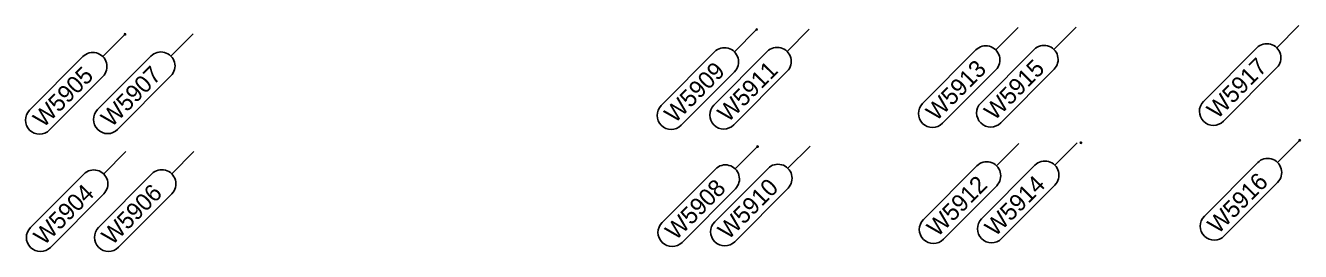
# Model space of a CAD drawing. Extents: x 12479652 to 12487250, y 9842710 to 9846560.
# Drawn here: x 12483353.2 to 12483446.2, y 9842743 to 9842759.5 of the extents above; entities that cross this region are included whole.
import ezdxf

# ---------------------------------------------------------------- set-up
doc = ezdxf.new("R2010")
doc.units = 0
doc.layers.add('_CIVIL_CONSTRUCTION', color=7, linetype='Continuous')
doc.layers.add('TextAlignmentLrg', color=7, linetype='Continuous')

msp = doc.modelspace()

# ---------------------------------------------------------------- linework, layer by layer
at = {"layer": '_CIVIL_CONSTRUCTION'}
for p, q in [((12483406.501, 9842759.196), (12483404.879, 9842757.565)), ((12483410.341, 9842759.225), (12483408.719, 9842757.594)), ((12483425.562, 9842759.339), (12483423.94, 9842757.707)), ((12483429.807, 9842759.37), (12483428.185, 9842757.739)), ((12483446.053, 9842759.492), (12483444.432, 9842757.86)), ((12483360.435, 9842758.852), (12483358.813, 9842757.221)), ((12483365.398, 9842758.889), (12483363.776, 9842757.258)), ((12483353.473, 9842753.304), (12483357.362, 9842757.216)), ((12483358.436, 9842753.341), (12483362.325, 9842757.254)), ((12483399.539, 9842753.648), (12483403.429, 9842757.561)), ((12483403.379, 9842753.676), (12483407.268, 9842757.589)), ((12483418.6, 9842753.79), (12483422.49, 9842757.703)), ((12483422.845, 9842753.822), (12483426.734, 9842757.735)), ((12483439.091, 9842753.943), (12483442.981, 9842757.856)), ((12483404.884, 9842756.114), (12483400.994, 9842752.201)), ((12483408.724, 9842756.143), (12483404.834, 9842752.23)), ((12483423.945, 9842756.256), (12483420.055, 9842752.344)), ((12483428.189, 9842756.288), (12483424.3, 9842752.375)), ((12483444.436, 9842756.409), (12483440.546, 9842752.497)), ((12483358.817, 9842755.77), (12483354.928, 9842751.857)), ((12483363.78, 9842755.807), (12483359.891, 9842751.894)), ((12483406.565, 9842750.641), (12483404.943, 9842749.009)), ((12483410.405, 9842750.686), (12483408.783, 9842749.055)), ((12483425.625, 9842750.867), (12483424.004, 9842749.236)), ((12483429.87, 9842750.918), (12483428.248, 9842749.286)), ((12483446.116, 9842751.11), (12483444.494, 9842749.479)), ((12483360.499, 9842750.274), (12483358.877, 9842748.643)), ((12483365.462, 9842750.286), (12483363.84, 9842748.655)), ((12483399.603, 9842745.092), (12483403.493, 9842749.005)), ((12483403.443, 9842745.138), (12483407.332, 9842749.051)), ((12483418.663, 9842745.319), (12483422.553, 9842749.231)), ((12483422.908, 9842745.369), (12483426.797, 9842749.282)), ((12483439.154, 9842745.562), (12483443.043, 9842749.475)), ((12483353.537, 9842744.726), (12483357.426, 9842748.639)), ((12483358.5, 9842744.738), (12483362.389, 9842748.65)), ((12483424.008, 9842747.785), (12483420.118, 9842743.872)), ((12483428.252, 9842747.835), (12483424.363, 9842743.923)), ((12483444.498, 9842748.028), (12483440.609, 9842744.116)), ((12483358.881, 9842747.192), (12483354.992, 9842743.279)), ((12483363.845, 9842747.204), (12483359.955, 9842743.291)), ((12483404.948, 9842747.559), (12483401.058, 9842743.646)), ((12483408.787, 9842747.604), (12483404.898, 9842743.691))]:
    msp.add_line(p, q, dxfattribs=at)
for centre, start, end in [((12483423.217, 9842756.98), 315.17021, 135.17022), ((12483427.462, 9842757.011), 315.17021, 135.17022), ((12483443.708, 9842757.133), 315.17021, 135.17022), ((12483358.09, 9842756.493), 315.17021, 135.17022), ((12483363.053, 9842756.53), 315.17021, 135.17022), ((12483404.156, 9842756.837), 315.17021, 135.17022), ((12483407.996, 9842756.866), 315.17021, 135.17022), ((12483359.163, 9842752.617), 135.17022, 315.17021), ((12483400.267, 9842752.924), 135.17022, 315.17021), ((12483404.106, 9842752.953), 135.17022, 315.17021), ((12483419.328, 9842753.067), 135.17022, 315.17021), ((12483423.572, 9842753.099), 135.17022, 315.17021), ((12483439.819, 9842753.22), 135.17022, 315.17021), ((12483354.2, 9842752.58), 135.17022, 315.17021), ((12483443.771, 9842748.752), 315.17021, 135.17022), ((12483358.154, 9842747.915), 315.17021, 135.17022), ((12483363.117, 9842747.927), 315.17021, 135.17022), ((12483404.22, 9842748.282), 315.17021, 135.17022), ((12483408.06, 9842748.327), 315.17021, 135.17022), ((12483423.28, 9842748.508), 315.17021, 135.17022), ((12483427.525, 9842748.559), 315.17021, 135.17022), ((12483400.331, 9842744.369), 135.17022, 315.17021), ((12483404.17, 9842744.415), 135.17022, 315.17021), ((12483419.391, 9842744.595), 135.17022, 315.17021), ((12483423.635, 9842744.646), 135.17022, 315.17021), ((12483439.881, 9842744.839), 135.17022, 315.17021), ((12483354.264, 9842744.003), 135.17022, 315.17021), ((12483359.227, 9842744.014), 135.17022, 315.17021)]:
    msp.add_arc(centre, 1.026, start, end, dxfattribs=at)
at = {"layer": 'TextAlignmentLrg'}
for centre in [(12483360.435, 9842758.852), (12483406.501, 9842759.196), (12483406.565, 9842750.641), (12483430.152, 9842750.921), (12483446.116, 9842751.11)]:
    msp.add_circle(centre, 0.05, dxfattribs=at)

# ---------------------------------------------------------------- texts
at = {"layer": '_CIVIL_CONSTRUCTION'}
for s, p in [('W5917', (12483440.101, 9842752.603)), ('W5905', (12483354.484, 9842751.965)), ('W5907', (12483359.446, 9842752.001)), ('W5909', (12483400.54, 9842752.298)), ('W5911', (12483404.414, 9842752.361)), ('W5913', (12483419.607, 9842752.447)), ('W5915', (12483423.856, 9842752.483)), ('W5916', (12483440.15, 9842744.208)), ('W5904', (12483354.529, 9842743.368)), ('W5906', (12483359.496, 9842743.384)), ('W5908', (12483400.602, 9842743.742)), ('W5910', (12483404.441, 9842743.786)), ('W5912', (12483419.682, 9842743.988)), ('W5914', (12483423.9, 9842744.011))]:
    msp.add_text(s, height=1.25, rotation=45.17021, dxfattribs=at).set_placement(p)

doc.saveas('drawing.dxf')
